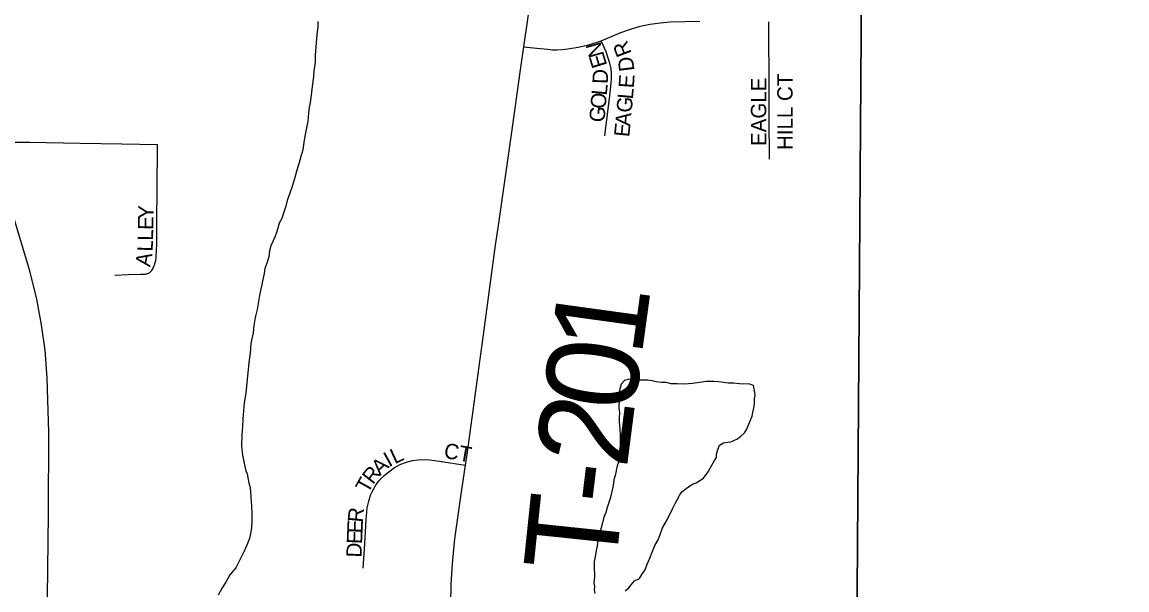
# Model space of a CAD drawing. Extents: x 0 to 68, y 0 to 52.9.
# Drawn here: x 26.586 to 27.244, y 18.957 to 19.295 of the extents above; entities that cross this region are included whole.
import ezdxf

# ---------------------------------------------------------------- set-up
doc = ezdxf.new("R2010")
doc.units = 0
for name, color, linetype in [('Default', 7, 'Continuous'), ('GM_X_Minor_Lake', 7, 'Continuous'), ('GM_X_Minor_River', 7, 'Continuous'), ('GM_X_Township_Road', 7, 'Continuous'), ('GM_X_Township_Road_Text', 7, 'Continuous'), ('GM_X_Township_Subdivision', 7, 'Continuous'), ('GM_X_Township_Subdivision_Text', 7, 'Continuous')]:
    doc.layers.add(name, color=color, linetype=linetype)

msp = doc.modelspace()

# ---------------------------------------------------------------- linework, layer by layer
at = {"layer": 'Default'}
for points in [[(27.08922, 19.81156), (27.08235, 18.84562), (26.12306, 18.85678), (26.13943, 19.82295)], [(27.08922, 19.81156), (28.06197, 19.7892), (28.0517, 18.82075), (27.08235, 18.84562)]]:
    msp.add_lwpolyline(points, close=True, dxfattribs=at)
for points in [[(26.60003, 18.90325), (26.60126, 19.00192), (26.60138, 19.05027), (26.60052, 19.08279), (26.59917, 19.09936), (26.59709, 19.11445), (26.59426, 19.12967), (26.59009, 19.14648), (26.57377, 19.20072), (26.5653, 19.22993), (26.55769, 19.25828), (26.55303, 19.28), (26.55009, 19.29902), (26.54837, 19.31117), (26.54726, 19.32798), (26.5464, 19.3702), (26.54815, 19.48654), (26.55251, 19.81661)], [(26.93063, 19.28351), (26.94234, 19.28851), (26.94803, 19.29051), (26.95381, 19.29218), (26.95971, 19.29345), (26.96567, 19.29429), (26.97168, 19.29475), (26.98937, 19.29524)], [(27.03087, 19.21298), (27.03068, 19.23774), (27.03067, 19.25271), (27.03049, 19.29485)], [(26.88419, 19.27998), (26.8923, 19.27907), (26.89869, 19.27847), (26.90163, 19.27816), (26.90418, 19.2782), (26.90701, 19.27837), (26.91066, 19.27878), (26.91674, 19.27979), (26.92323, 19.28121), (26.93063, 19.28351)], [(26.93268, 19.22691), (26.93594, 19.25247), (26.93676, 19.26072), (26.93678, 19.2626), (26.93663, 19.26483), (26.93647, 19.2666), (26.93617, 19.26853), (26.93577, 19.27012), (26.93478, 19.27325), (26.93346, 19.27705), (26.93063, 19.28351)], [(26.54564, 19.2234), (26.55397, 19.22322), (26.59003, 19.22314), (26.62004, 19.22248), (26.645, 19.2222), (26.66629, 19.22174)], [(26.66265, 19.14664), (26.66346, 19.14785), (26.6639, 19.14881), (26.66426, 19.14977), (26.66458, 19.15056), (26.6649, 19.15145), (26.66509, 19.15212), (26.6652, 19.15259), (26.66529, 19.15336), (26.66533, 19.15402), (26.66545, 19.15562), (26.66557, 19.15767), (26.66572, 19.16366), (26.66587, 19.17735), (26.66602, 19.1942), (26.66629, 19.22174)], [(26.64084, 19.14405), (26.64885, 19.14441), (26.6561, 19.14456), (26.65733, 19.14458), (26.65792, 19.14462), (26.65864, 19.14467), (26.65915, 19.14473), (26.65974, 19.1448), (26.66037, 19.14499), (26.66098, 19.14524), (26.66143, 19.1455), (26.6618, 19.14579), (26.66225, 19.1462), (26.66265, 19.14664)]]:
    msp.add_lwpolyline(points, dxfattribs=at)
at = {"layer": 'GM_X_Minor_Lake'}
for points in [[(27.01911, 19.07908), (27.01288, 19.07921), (27.01288, 19.07921), (27.00959, 19.07964), (27.00629, 19.07971), (27.00337, 19.08013), (27.00044, 19.08056), (26.99788, 19.08061), (26.99568, 19.08065), (26.99311, 19.08071), (26.98907, 19.08006), (26.98502, 19.07941), (26.98025, 19.07913), (26.97585, 19.07922), (26.97219, 19.0793), (26.96927, 19.08009), (26.96634, 19.08015), (26.96341, 19.08057), (26.96085, 19.08099), (26.9583, 19.08141), (26.95646, 19.08145), (26.9517, 19.08154), (26.94914, 19.08196), (26.94694, 19.082), (26.94436, 19.08132), (26.94249, 19.07916), (26.94169, 19.07625), (26.94129, 19.07442), (26.94125, 19.07222), (26.94121, 19.07039), (26.94117, 19.06856), (26.94113, 19.06673), (26.94109, 19.06453), (26.94141, 19.06232), (26.94134, 19.05903), (26.9413, 19.05683), (26.94158, 19.05242), (26.94186, 19.04839), (26.94177, 19.04399), (26.94168, 19.03959), (26.94124, 19.03557), (26.94081, 19.03265), (26.94003, 19.03046), (26.93963, 19.02864), (26.93922, 19.02645), (26.93881, 19.02462), (26.93803, 19.02207), (26.9376, 19.01878), (26.93677, 19.0144), (26.93597, 19.01112), (26.93519, 19.00857), (26.93403, 19.00566), (26.93324, 19.00274), (26.93208, 18.99984), (26.93128, 18.99655), (26.93049, 18.99364), (26.9297, 18.99109), (26.92892, 18.98854), (26.9285, 18.98598), (26.92807, 18.98269), (26.92765, 18.98013), (26.92723, 18.97757), (26.92682, 18.97539), (26.92641, 18.97356), (26.92637, 18.97136), (26.92659, 18.96403), (26.92616, 18.9611), (26.92648, 18.95853), (26.92644, 18.9567), (26.92676, 18.95449)], [(26.98044, 19.01645), (26.98342, 19.01859), (26.98528, 19.01966), (26.98712, 19.02035), (26.98935, 19.02177), (26.99158, 19.02319), (26.99422, 19.02681), (26.9965, 19.03079), (26.99803, 19.03369), (26.99916, 19.0355), (26.9992, 19.03733), (26.99999, 19.04025), (27.00114, 19.04279), (27.00337, 19.04422), (27.00594, 19.04453), (27.00778, 19.04486), (27.00963, 19.04555), (27.01185, 19.04661), (27.01371, 19.04804), (27.01596, 19.05019), (27.01709, 19.052), (27.01787, 19.05382), (27.02056, 19.05999), (27.02097, 19.06219), (27.02178, 19.06584), (27.02182, 19.06803), (27.02187, 19.0706), (27.02228, 19.07242), (27.02197, 19.07536), (27.02129, 19.07831), (27.01911, 19.07908)], [(26.94475, 18.95597), (26.94699, 18.95775), (26.94849, 18.95956), (26.95038, 18.96208), (26.95334, 18.96349), (26.95523, 18.96638), (26.95674, 18.96855), (26.95791, 18.97183), (26.95945, 18.97546), (26.96099, 18.97909), (26.96254, 18.9831), (26.96444, 18.98636), (26.9656, 18.98963), (26.96715, 18.99363), (26.96981, 18.99834), (26.97325, 19.00524), (26.97478, 19.00851), (26.97593, 19.01068), (26.97744, 19.01322), (26.97858, 19.01503), (26.98044, 19.01645)]]:
    msp.add_lwpolyline(points, dxfattribs=at)
at = {"layer": 'GM_X_Minor_River'}
msp.add_lwpolyline([(26.76171, 19.29502), (26.76165, 19.29172), (26.76119, 19.28734), (26.76021, 19.27489), (26.76012, 19.27086), (26.7597, 19.26794), (26.75928, 19.26538), (26.75922, 19.26245), (26.75879, 19.25916), (26.75836, 19.25624), (26.75793, 19.25295), (26.75749, 19.24966), (26.75707, 19.24673), (26.75664, 19.24381), (26.75621, 19.24052), (26.75575, 19.23576), (26.75493, 19.23175), (26.75412, 19.22773), (26.75368, 19.22444), (26.75326, 19.22152), (26.75283, 19.2186), (26.75165, 19.21459), (26.75046, 19.21021), (26.74929, 19.20657), (26.7481, 19.2022), (26.74654, 19.19746), (26.74497, 19.19273), (26.74342, 19.18837), (26.74262, 19.18508), (26.74145, 19.18144), (26.74027, 19.1778), (26.73875, 19.1749), (26.73795, 19.17198), (26.73717, 19.16943), (26.73601, 19.16652), (26.73486, 19.16398), (26.73371, 19.16144), (26.73292, 19.15852), (26.73247, 19.15486), (26.7313, 19.15122), (26.73013, 19.14795), (26.72971, 19.14502), (26.7289, 19.14137), (26.72809, 19.13736), (26.72726, 19.13298), (26.72644, 19.12823), (26.72561, 19.12348), (26.72441, 19.11874), (26.72358, 19.11399), (26.72313, 19.10961), (26.7219, 19.1034), (26.72141, 19.09754), (26.72057, 19.09206), (26.71873, 19.07377), (26.71788, 19.06793), (26.71742, 19.06317), (26.71696, 19.05841), (26.71686, 19.05365), (26.7164, 19.0489), (26.71626, 19.0423), (26.71688, 19.03679), (26.71754, 19.03311), (26.71821, 19.03017), (26.7189, 19.02759), (26.71959, 19.02574), (26.72026, 19.02243), (26.72058, 19.02022), (26.72128, 19.01838), (26.72158, 19.01544), (26.72188, 19.01177), (26.72213, 19.00626), (26.72242, 19.00223), (26.72236, 18.9993), (26.72231, 18.9971), (26.72225, 18.9938), (26.72183, 18.99124), (26.72101, 18.98723), (26.71946, 18.98323), (26.71792, 18.97959), (26.71564, 18.97524), (26.71296, 18.9698), (26.70921, 18.96548), (26.70692, 18.96112), (26.70465, 18.95787), (26.70236, 18.95352)], dxfattribs=at)
at = {"layer": 'GM_X_Township_Road'}
for points in [[(26.8917, 19.33089), (26.88419, 19.27998)], [(26.88419, 19.27998), (26.88226, 19.26632), (26.87698, 19.22772), (26.86925, 19.17362)], [(26.86925, 19.17362), (26.86745, 19.1618), (26.86071, 19.11139), (26.85045, 19.03729), (26.84951, 19.03089)], [(26.84951, 19.03089), (26.84686, 19.0136), (26.84322, 18.98693), (26.84169, 18.97204), (26.84103, 18.96009), (26.84085, 18.94813), (26.83994, 18.85052)]]:
    msp.add_lwpolyline(points, dxfattribs=at)
at = {"layer": 'GM_X_Township_Subdivision'}
msp.add_lwpolyline([(26.78875, 18.96947), (26.78949, 18.98083), (26.79056, 18.99823), (26.7912, 19.00541), (26.79202, 19.00953), (26.79313, 19.01295), (26.79463, 19.01622), (26.79651, 19.01929), (26.79874, 19.02212), (26.80129, 19.02468), (26.80406, 19.02698), (26.8075, 19.02941), (26.8112, 19.03139), (26.81455, 19.0327), (26.81803, 19.03363), (26.8216, 19.03413), (26.8252, 19.03425), (26.82819, 19.03408), (26.83414, 19.03328), (26.84951, 19.03089)], dxfattribs=at)

# ---------------------------------------------------------------- texts
at = {"layer": 'Default'}
for s, height, rotation, p in [('N', 0.00914, 105.75927, (26.93234, 19.27509)), ('R', 0.00914, 110.84081, (26.94885, 19.2761)), ('E', 0.00914, 107.09753, (26.93422, 19.269)), ('D', 0.00914, 97.19916, (26.95043, 19.26582)), ('D', 0.00914, 88.67533, (26.93447, 19.2578)), ('E', 0.00914, 86.53133, (26.94999, 19.25514)), ('EAGLE', 0.009135, 90, (27.0289, 19.2209)), ('HILL CT', 0.009135, 90, (27.04461, 19.21849)), ('L', 0.00914, 84.90969, (26.93386, 19.25074)), ('L', 0.00914, 84.93437, (26.9494, 19.24846)), ('O', 0.00914, 84.90228, (26.93315, 19.24273)), ('G', 0.00914, 84.60876, (26.94864, 19.2404)), ('G', 0.00914, 84.90055, (26.93243, 19.23472)), ('A', 0.00914, 84.56381, (26.94788, 19.23239)), ('E', 0.00914, 84.55577, (26.94727, 19.22598)), ('Y', 0.00914, 88.71045, (26.66379, 19.17728)), ('E', 0.00914, 88.70164, (26.66364, 19.17085)), ('L', 0.00914, 88.6879, (26.6635, 19.16442)), ('L', 0.00914, 88.2981, (26.66331, 19.15793)), ('A', 0.00914, 80.1604, (26.66179, 19.1486))]:
    msp.add_text(s, height=height, rotation=rotation, dxfattribs=at).set_placement(p)
at = {"layer": 'GM_X_Township_Road_Text'}
for s, rotation, p in [('1', 82.16943, (26.95455, 19.09497)), ('0', 82.26952, (26.95002, 19.06153)), ('2', 82.64778, (26.94571, 19.02814)), ('-', 83.05894, (26.943, 19.0059)), ('T', 84.028, (26.93876, 18.96536))]:
    msp.add_text(s, height=0.05481, rotation=rotation, dxfattribs=at).set_placement(p)
at = {"layer": 'GM_X_Township_Subdivision_Text'}
for s, height, rotation, p in [('CT', 0.009135, 349.99642, (26.83637, 19.03528)), ('I', 0.00914, 28.99089, (26.80416, 19.0295)), ('L', 0.00914, 25.02514, (26.80752, 19.03137)), ('A', 0.00914, 43.06767, (26.79877, 19.02436)), ('T', 0.00914, 60.77024, (26.79165, 19.01361)), ('R', 0.00914, 52.17825, (26.79459, 19.01892)), ('R', 0.00914, 84.69782, (26.78855, 18.99651)), ('E', 0.00914, 87.70392, (26.7883, 18.99021)), ('E', 0.00914, 87.70392, (26.78805, 18.98378)), ('D', 0.00914, 87.70414, (26.78773, 18.97575))]:
    msp.add_text(s, height=height, rotation=rotation, dxfattribs=at).set_placement(p)

doc.saveas('drawing.dxf')
